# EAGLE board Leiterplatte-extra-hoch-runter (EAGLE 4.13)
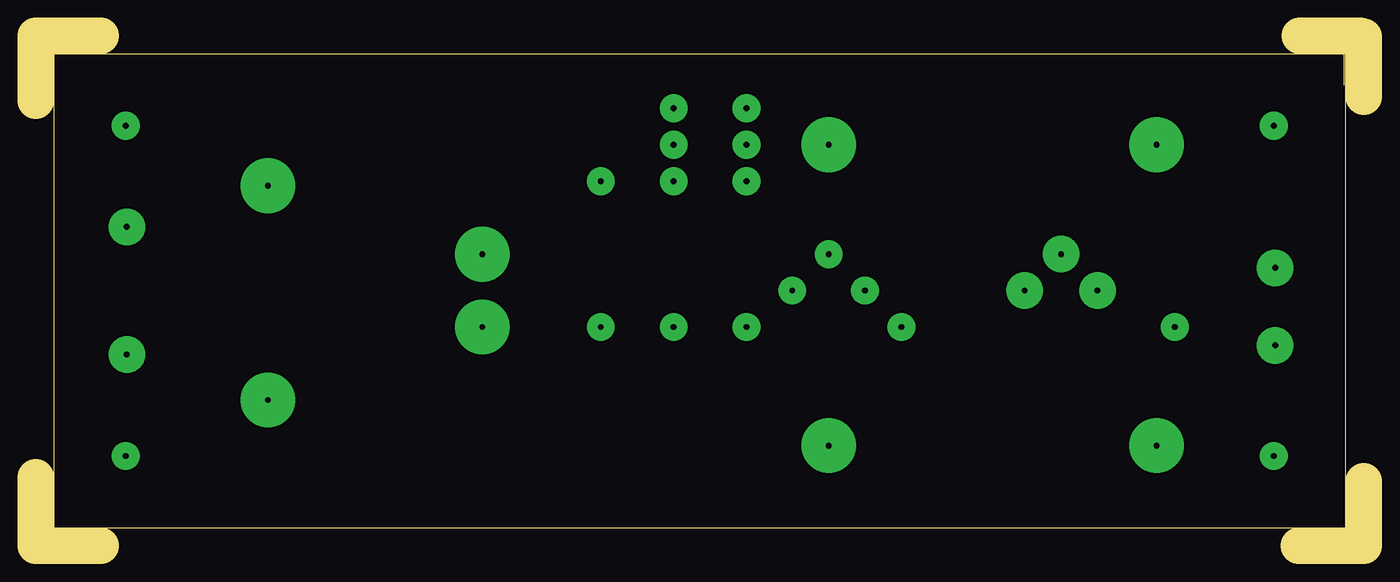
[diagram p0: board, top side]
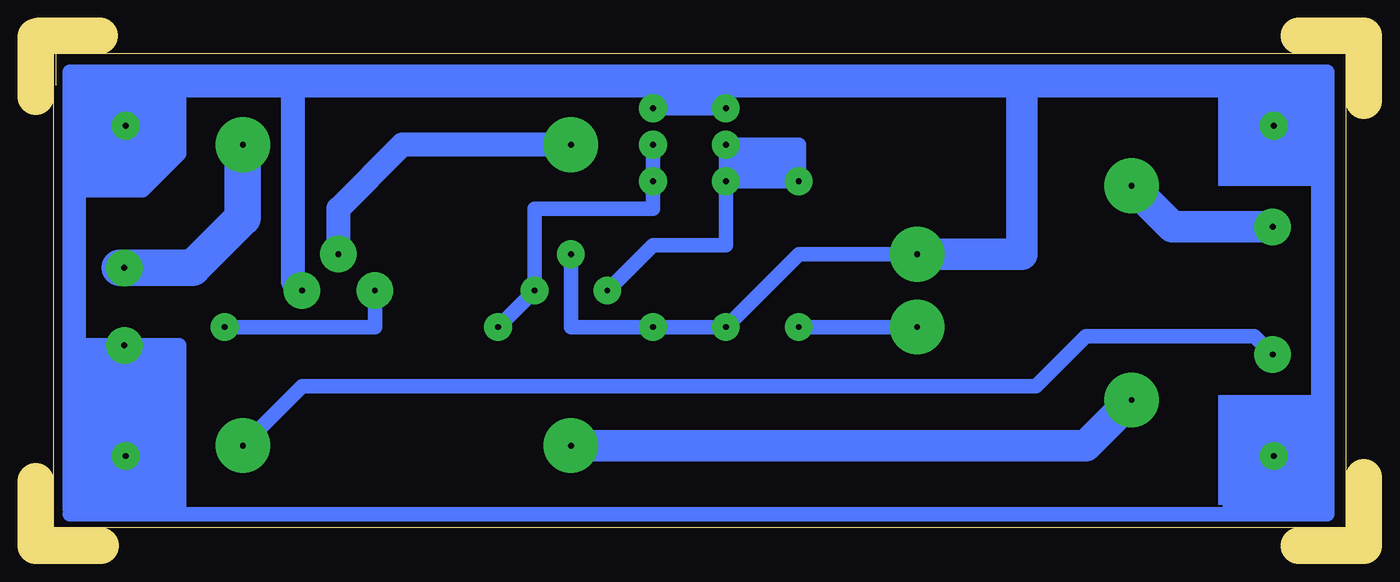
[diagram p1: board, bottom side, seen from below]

Size 92.5 x 35.5 mm. Coordinates in mm from the lower left corner, seen from the top.
Outline: 91.25,34.25 91.25,1.25 1.25,1.25 1.25,34.25
Outline: 0,31 0,35.5 4.5,35.5
Outline: 0,0.25 0,4.75
Outline: 4.5,0 0,0
Outline: 92.5,35.43 92.5,31.25
Outline: 92.5,4.5 92.5,0 88,0
Outline: 88.07,35.5 92.25,35.5
Outline: 1.25,34.27 91.1,34.27 91.1,32.05
Copper layers (1*16): Top 0.035mm / dielectric 1.5mm / Bottom 0.035mm
Design rules "default": minimum track width 10mil, minimum drill 24mil, track to track 8mil, track to pad 8mil, pad to pad 8mil, via to via 8mil, smd to smd 8mil, copper to edge 40mil, drill to drill 8mil, minimum pad ring 10mil, minimum via ring 8mil, stop-mask expansion 4mil, vias tented up to drill 0mil, thermal gap 10mil

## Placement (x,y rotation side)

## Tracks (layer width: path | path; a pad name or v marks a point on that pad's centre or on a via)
S$1  (via drill 0.4 pad 1.93)
  other vias: 6.25,6.25
S$2  (via drill 0.4 pad 1.93)
  other vias: 6.25,29.25
S$3  (via drill 0.4 pad 1.93)
  other vias: 86.25,6.25
S$4  (via drill 0.4 pad 1.93)
  other vias: 86.25,29.25
S$5  (via drill 0.4 pad 1.93, 0.4 pad 2.54)
  Bottom 1.016: v68.88,17.76 68.88,15.22 v79.36,15.22
S$7  (via drill 0.4 pad 1.93, 0.4 pad 3.81)
  Bottom 1.016: v39.35,15.22 v31.09,15.22
S$8  (via drill 0.4 pad 2.54, 0.4 pad 3.81)
  Bottom 1.676: v55.23,27.92 66.97,27.92 71.42,23.48 v71.42,20.3
S$9  (via drill 0.4 pad 3.81)
  Bottom 2.184: 26.02,6.96 28.24,6.96 | 28.24,6.96 v55.23,6.96 | v16.17,10.14 19.35,6.96 28.24,6.96
S$10  (via drill 0.4 pad 2.54, 0.4 pad 3.81)
  Bottom 1.016: 78.08,22.84 78.08,25.7 | v86.34,19.35 83.8,19.35 81.58,19.35
  Bottom 2.54: 78.08,25.7 v78.08,27.92 78.08,22.84 81.58,19.35 83.8,19.35 86.66,19.35
S$15  (via drill 0.4 pad 2.54, 0.4 pad 3.81)
  Bottom 2.184: v6.33,22.2 13.31,22.2 v16.17,25.06
S$17  (via drill 0.4 pad 2.54, 0.4 pad 3.81)
  Bottom 1.016: v78.08,6.96 73.96,11.09 22.84,11.09 19.35,14.59 7.6,14.59 v6.33,13.31
S$21  (via drill 0.4 pad 1.93)
  Bottom 1.016: v44.43,25.38 v44.43,27.92 39.35,27.92 v39.35,25.38 v44.43,25.38 | v44.43,25.38 44.43,20.93 49.51,20.93 v52.69,17.76
S$22  (via drill 0.4 pad 2.54)
  Bottom 1.016: 89.52,24.11 89.52,13.95 v86.34,13.95 82.53,13.95 82.53,2.52
S$23  (via drill 0.4 pad 1.93, 0.4 pad 3.81)
  Bottom 1.016: v55.23,20.3 55.23,15.22 v49.51,15.22 v44.43,15.22 39.35,20.3 v31.09,20.3
  Bottom 2.184: v31.09,20.3 23.79,20.3 23.79,32.05
S$25  (via drill 0.4 pad 1.93)
  Bottom 1.016: 44.43,32.36 v44.43,30.46 v49.51,30.46 49.51,32.05
S$26  (via drill 0.4 pad 1.93)
  Bottom 1.016: v49.51,27.92 v49.51,25.38 49.51,23.48 57.77,23.48 v57.77,17.76 v60.3,15.22
S$28  (via drill 0.4 pad 2.54)
  Bottom 1.016: 89.83,24.75 85.07,24.75 82.53,27.29 82.53,31.73 | 82.53,31.73 82.53,32.36 | 77.13,31.73 78.08,31.73 | 77.13,31.73 82.53,31.73 | 9.19,31.73 74.59,31.73 77.13,31.73
  Bottom 1.676: v73.96,17.76 74.59,18.39 74.59,31.73
S$34
  Bottom 1.016: 3.16,33 3.16,9.51 | 90.15,2.52 90.15,33 3.16,33 | 3.16,33 2.52,33 2.52,3.16 | 2.52,3.16 2.52,2.84 | 2.52,3.16 2.52,2.2 14.27,2.2 | 14.27,2.2 90.15,2.2 | 14.27,2.2 13,2.2
S$42
  Bottom 1.016: 27.92,32.36 27.92,32.05
(copper drawn outside any net)
  shapes: Bottom area x13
